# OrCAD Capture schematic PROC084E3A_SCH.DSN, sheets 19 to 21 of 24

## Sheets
19 18. RS485 INTERFACE: size C; title: RS485 INTERFACE
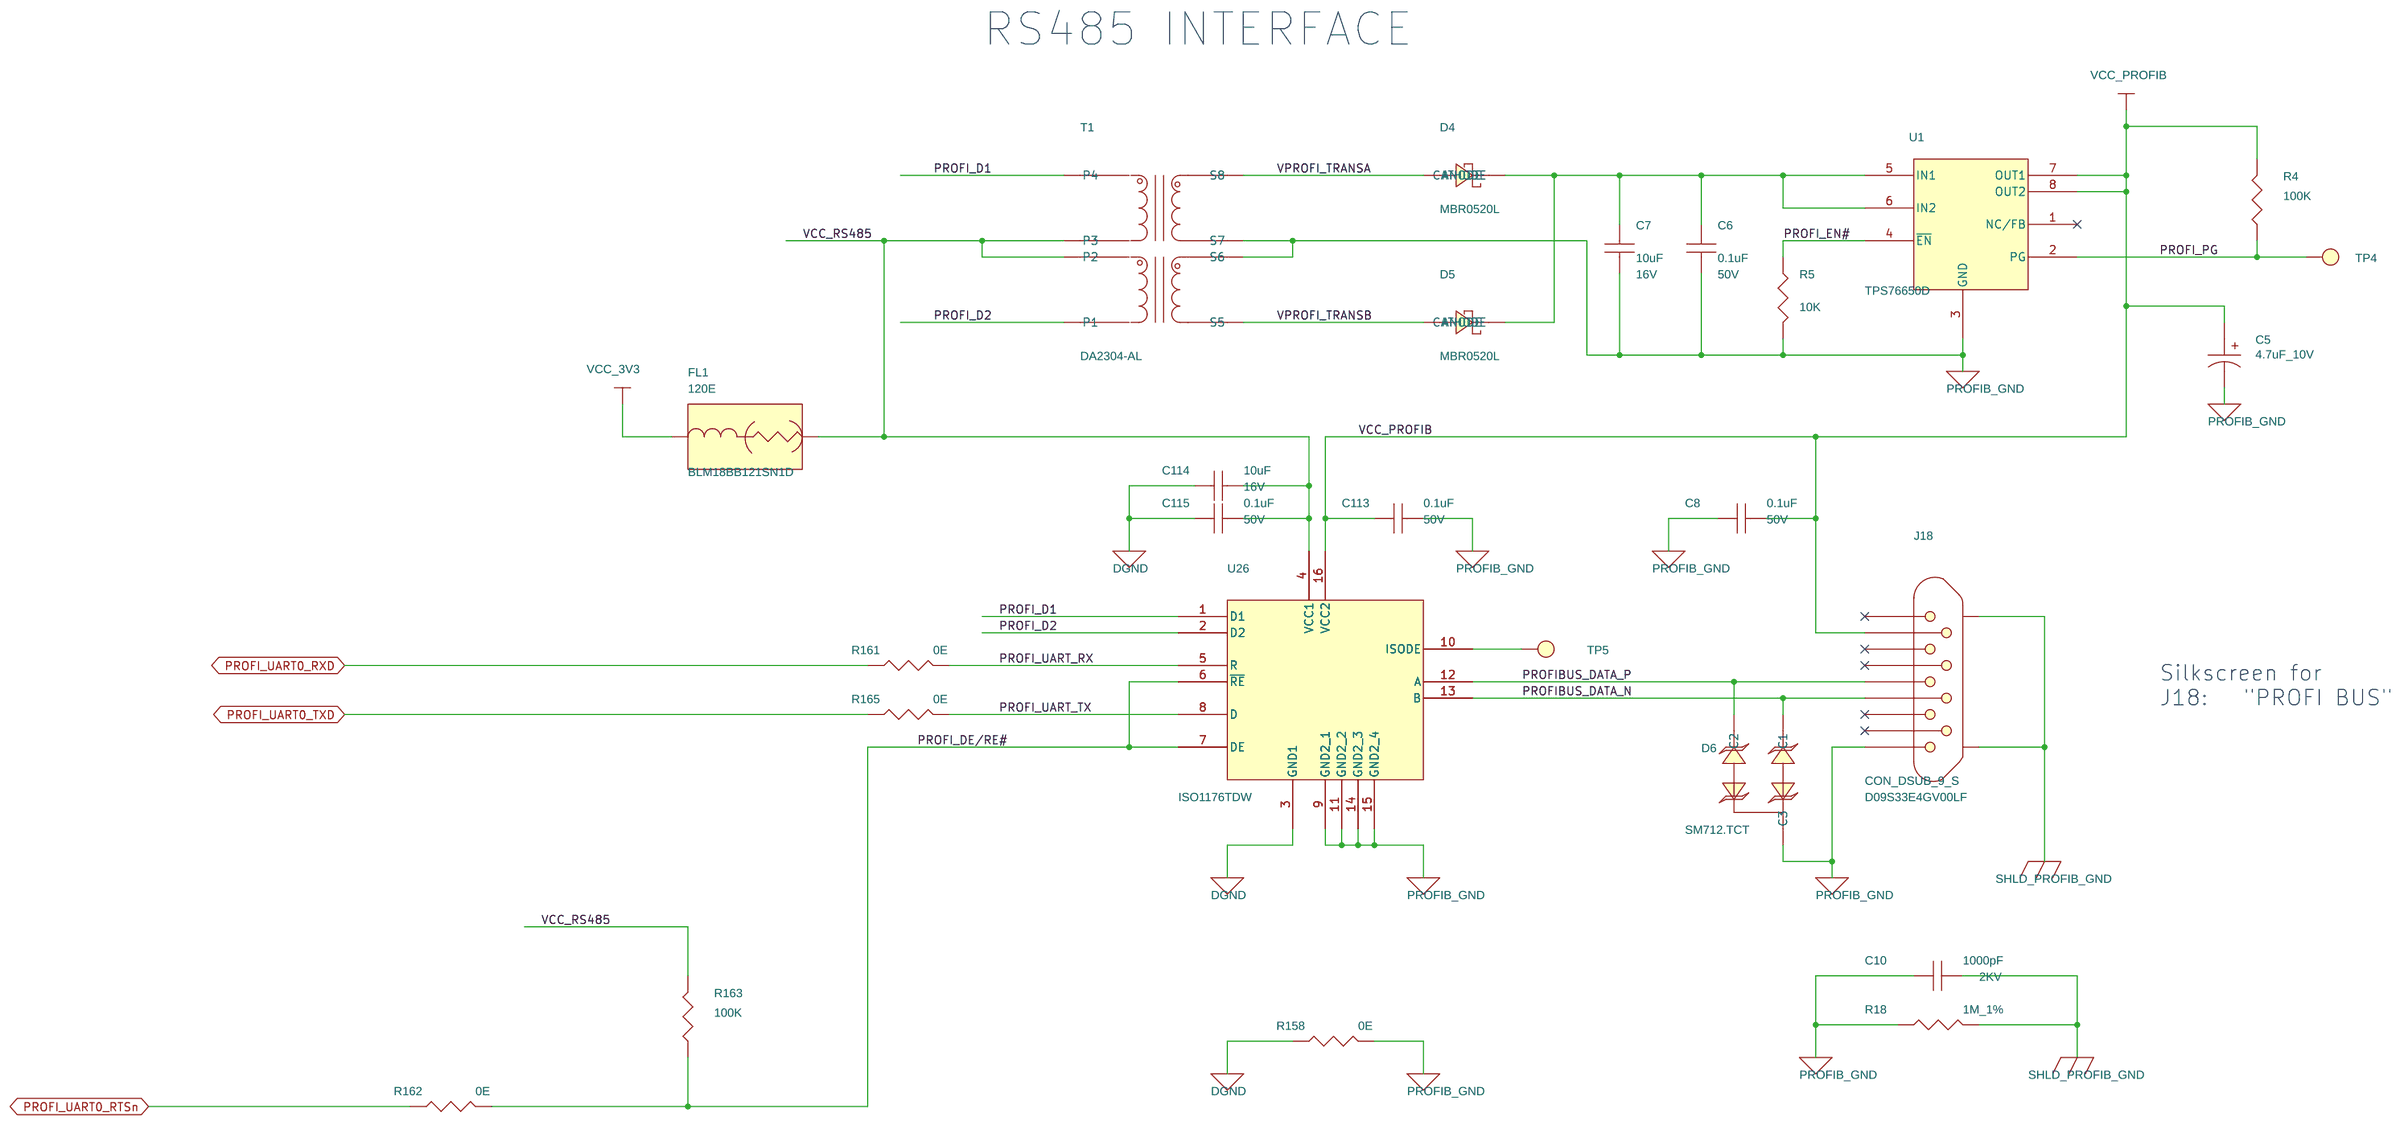
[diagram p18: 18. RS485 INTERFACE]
20 20. BOOSTERPACK HEADER: size C; title: BOOSTERPACK HEADER
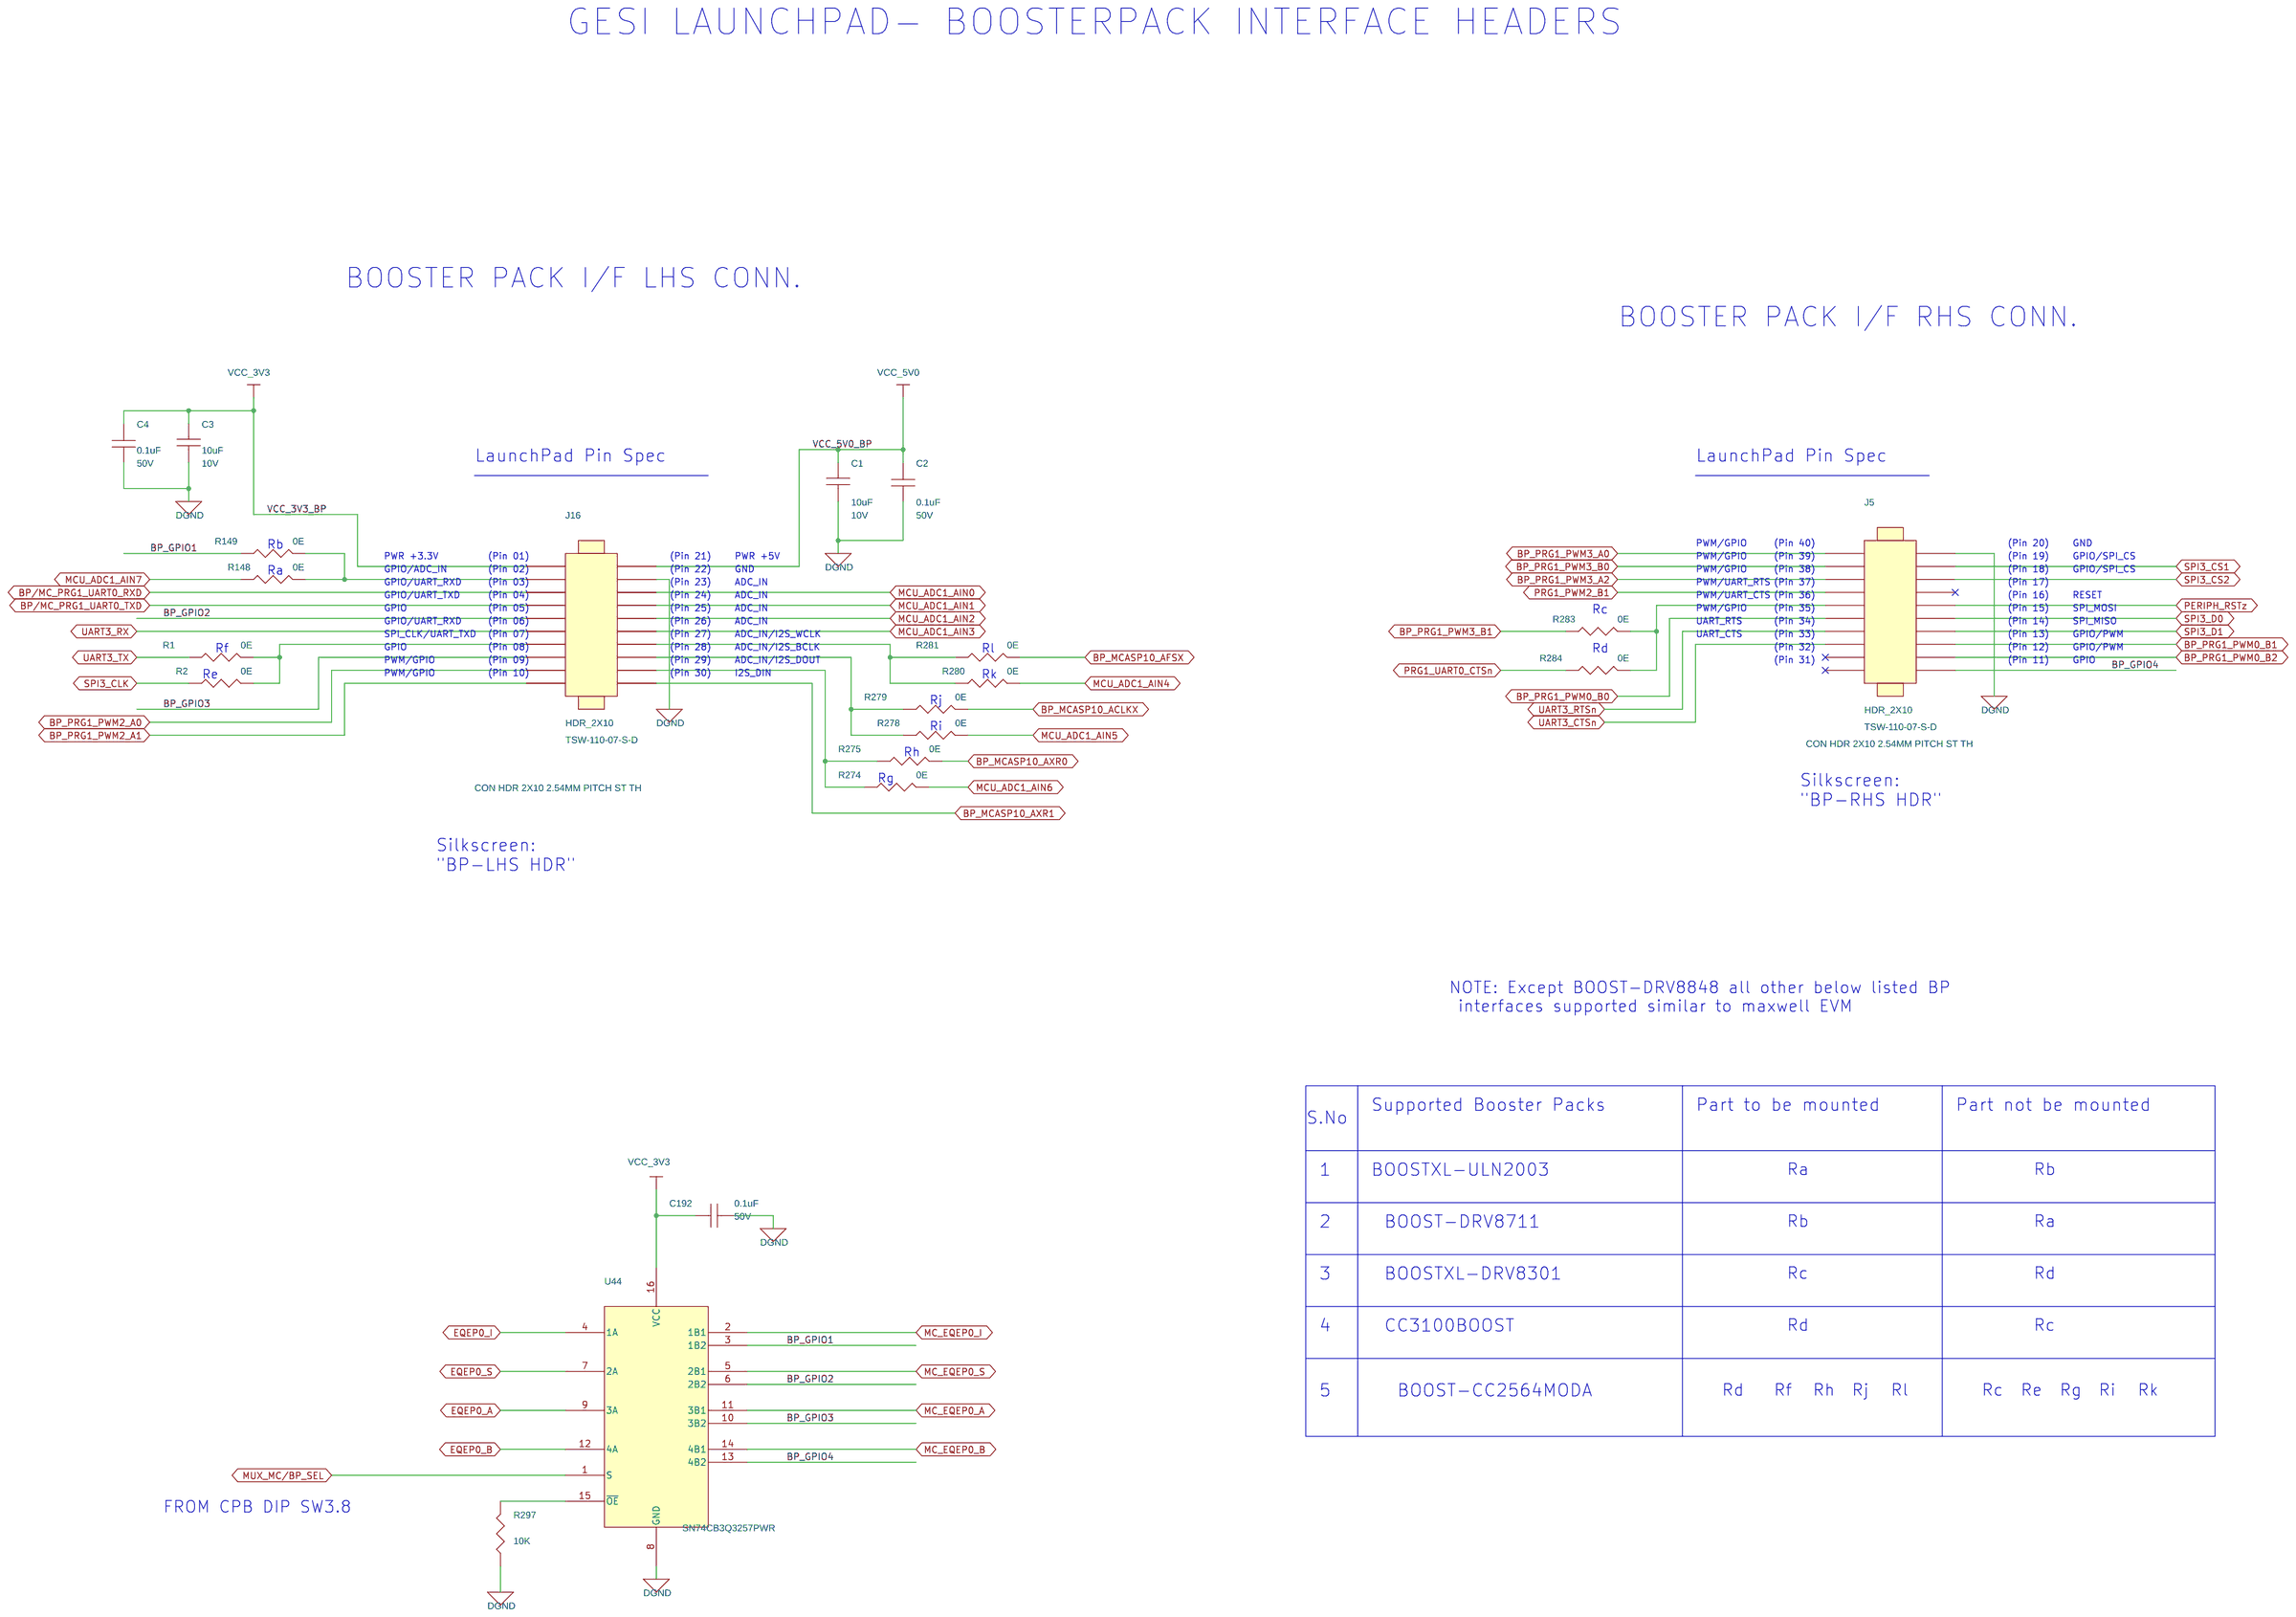
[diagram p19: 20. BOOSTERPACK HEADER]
21 21. ADC_IN: size C; title: ADC IN
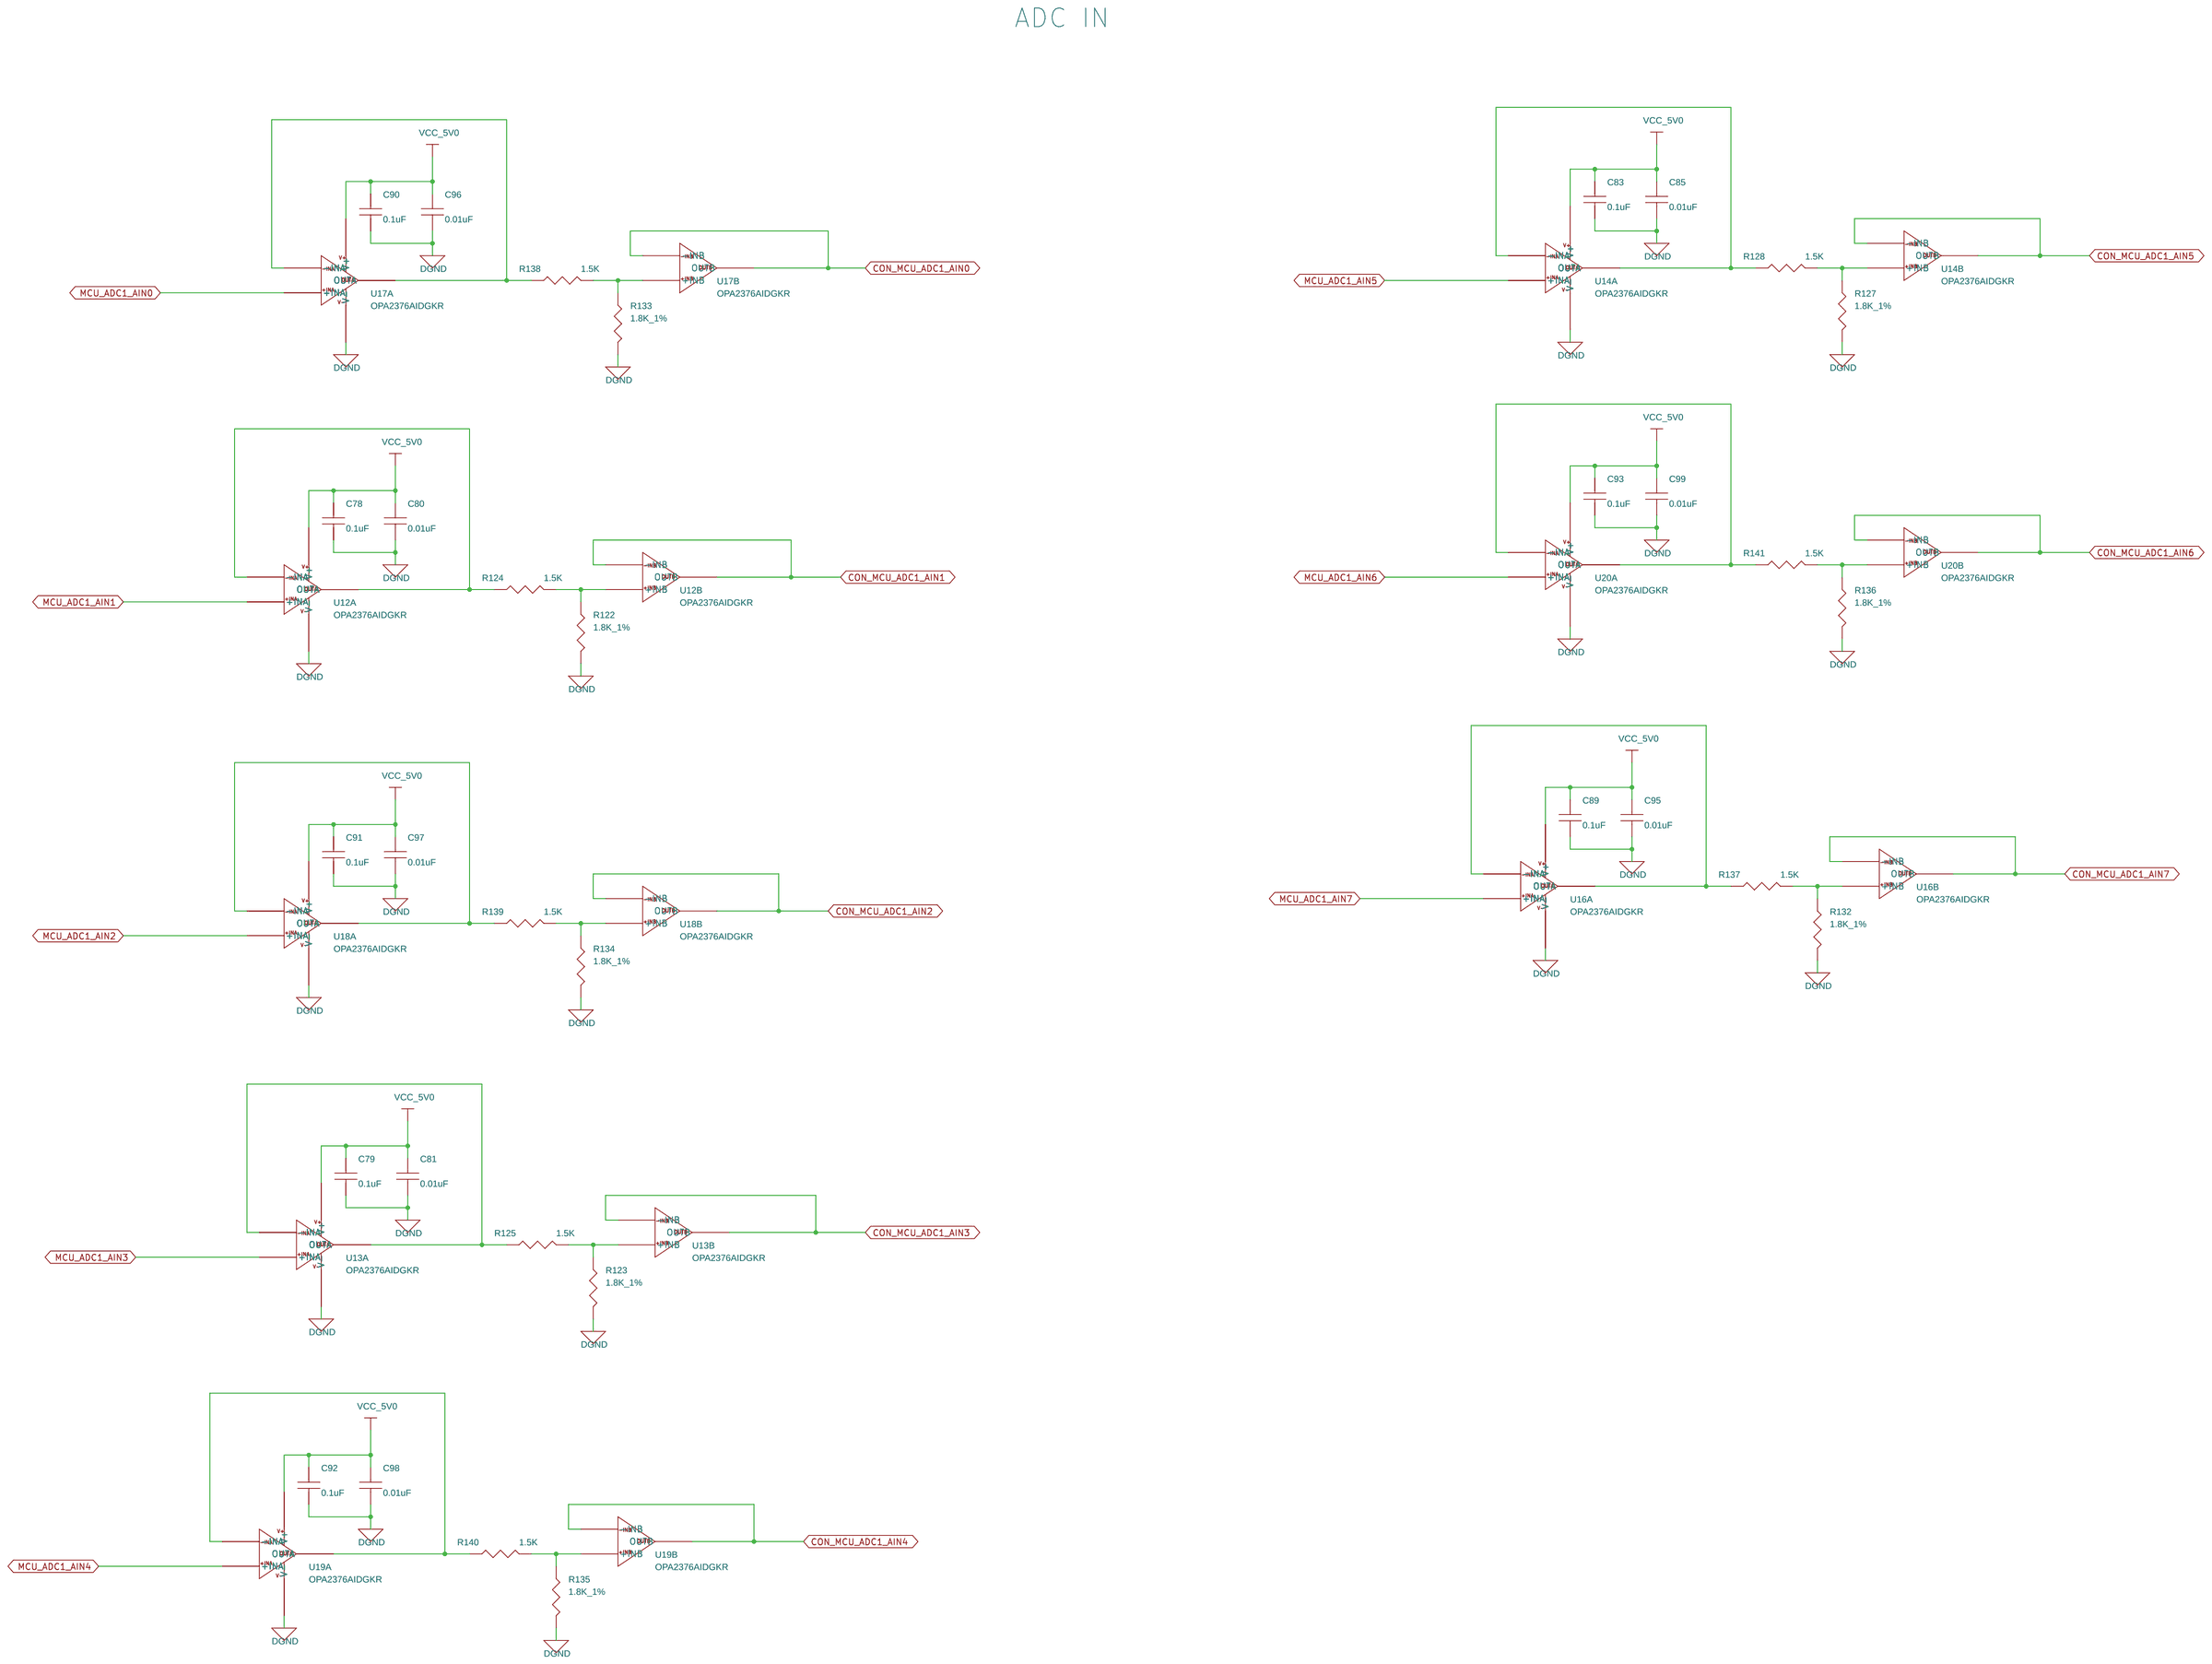
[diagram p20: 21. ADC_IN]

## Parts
sheet 18. RS485 INTERFACE
C5  4.7uF_10V  [CAPT3216A_2]
C6  0.1uF  [CAP0402_0-75]
C7  10uF  [CAP0805_1-5]
C8  0.1uF  [CAP0402_0-75]
C10  1000pF  [CAP1206_1-75]
C113  0.1uF  [CAP0402_0-75]
C114  10uF  [CAP0805_1-5]
C115  0.1uF  [CAP0402_0-75]
D4  MBR0520L  [DIO_SOD123]
D5  MBR0520L  [DIO_SOD123]
D6  SM712.TCT  [DIO_SOT23_123]
FL1  120E  [EMIFIL_BLM18A_0603]
J18  CON_DSUB_9_S  [CON_DB9_D09S33E4GV_S_R_T]
R4  100K  [RES0402_0-5]
R5  10K  [RES0402_0-5]
R18  1M_1%  [RES0805_0-75]
R158  0E  [RES0402_0-5]
R161  0E  [RES0402_0-5]
R162  0E  [RES0402_0-5]
R163  100K  [RES0402_0-5]
R165  0E  [RES0402_0-5]
T1  DA2304-AL  [XFMR8_DA2303-A_320X390_SMD_6]
TP4  TP40_SMD  [TP40_SMD]
TP5  TP40_SMD  [TP40_SMD]
U1  TPS76650D  [SOIC8]
U26  ISO1176TDW  [SOIC16_W]
sheet 20. BOOSTERPACK HEADER
C1  10uF  [CAP0402_0-75]
C2  0.1uF  [CAP0402_0-75]
C3  10uF  [CAP0402_0-75]
C4  0.1uF  [CAP0402_0-75]
C192  0.1uF  [CAP0402_0-75]
J5  HDR_2X10  [HDR_2X10_TSW_100_S_T]
J16  HDR_2X10  [HDR_2X10_TSW_100_S_T]
R1  0E  [RES0402_0-5]
R2  0E  [RES0402_0-5]
R148  0E  [RES0402_0-5]
R149  0E  [RES0402_0-5]
R274  0E  [RES0402_0-5]
R275  0E  [RES0402_0-5]
R278  0E  [RES0402_0-5]
R279  0E  [RES0402_0-5]
R280  0E  [RES0402_0-5]
R281  0E  [RES0402_0-5]
R283  0E  [RES0402_0-5]
R284  0E  [RES0402_0-5]
R297  10K  [RES0402_0-5]
U44  SN74CB3Q3257PWR  [TSSOP16_25-59_205X180]
sheet 21. ADC_IN
C78  0.1uF  [CAP0402_0-75]
C79  0.1uF  [CAP0402_0-75]
C80  0.01uF  [CAP0402_0-75]
C81  0.01uF  [CAP0402_0-75]
C83  0.1uF  [CAP0402_0-75]
C85  0.01uF  [CAP0402_0-75]
C89  0.1uF  [CAP0402_0-75]
C90  0.1uF  [CAP0402_0-75]
C91  0.1uF  [CAP0402_0-75]
C92  0.1uF  [CAP0402_0-75]
C93  0.1uF  [CAP0402_0-75]
C95  0.01uF  [CAP0402_0-75]
C96  0.01uF  [CAP0402_0-75]
C97  0.01uF  [CAP0402_0-75]
C98  0.01uF  [CAP0402_0-75]
C99  0.01uF  [CAP0402_0-75]
R122  1.8K_1%  [RES0402_0-5]
R123  1.8K_1%  [RES0402_0-5]
R124  1.5K  [RES0402_0-5]
R125  1.5K  [RES0402_0-5]
R127  1.8K_1%  [RES0402_0-5]
R128  1.5K  [RES0402_0-5]
R132  1.8K_1%  [RES0402_0-5]
R133  1.8K_1%  [RES0402_0-5]
R134  1.8K_1%  [RES0402_0-5]
R135  1.8K_1%  [RES0402_0-5]
R136  1.8K_1%  [RES0402_0-5]
R137  1.5K  [RES0402_0-5]
R138  1.5K  [RES0402_0-5]
R139  1.5K  [RES0402_0-5]
R140  1.5K  [RES0402_0-5]
R141  1.5K  [RES0402_0-5]
U12  OPA2376AIDGKR  [VSSOP8_25-59_120X120_1-1]  (sections A,B)
U13  OPA2376AIDGKR  [VSSOP8_25-59_120X120_1-1]  (sections A,B)
U14  OPA2376AIDGKR  [VSSOP8_25-59_120X120_1-1]  (sections A,B)
U16  OPA2376AIDGKR  [VSSOP8_25-59_120X120_1-1]  (sections A,B)
U17  OPA2376AIDGKR  [VSSOP8_25-59_120X120_1-1]  (sections A,B)
U18  OPA2376AIDGKR  [VSSOP8_25-59_120X120_1-1]  (sections A,B)
U19  OPA2376AIDGKR  [VSSOP8_25-59_120X120_1-1]  (sections A,B)
U20  OPA2376AIDGKR  [VSSOP8_25-59_120X120_1-1]  (sections A,B)

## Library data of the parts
C5 = CAP_POL: CAP TANTALUM 4.7uF 10V 10% ESR 5E A3216; Chkd/date: MANIRAJA/161017; Crtd /date: MAZHAR/080806; Custom_Duty: 15%; Customs_HS_Code: 85322990; Distributor_name: DIGIKEY; Distributor_part_number: 399-3696-1-ND; Footprint Path: Y:\MIS_DATABASE\Library\ALTIUM_TOOL\PCB_FOOTPRINTS\Altium_Footprint_Lib.PcbLib; Height: 1.80MM; Library Path: Y:\MIS_DATABASE\Library\ALTIUM_TOOL\SCHEMATICS_PARTS\MS_DISCRETE_Library.schlib; Mfr_name: KEMET; Mfr_part_number: T491A475K010AT; Mistral Part No: 120009080027-R; Package: A3216; Part_type: CAPACITORS\TANTALUM; Project: SVDO_RMB_MMA; RoHS: RoHS; Temperature: -55°C+125°C; Tolerance: 10%; Voltage: 10V; Wattage: NA; Weight: 16.2mg; Datasheet: Y:\MIS_DATABASE\DATASHEETS\CAPACITORS\KEMET_T491_MAR18.PDF
C2 C4 C6 C8 C113 C115 C192 = CAP: CAP CERAMIC 0.1uF 50V 10% X7R 0402; Chkd/date: VASANTHA/281216; Crtd /date: CHAITHANYA/051011; Custom_Duty: 15%; Customs_HS_Code: 85322990; Distributor_name: DIGIKEY; Distributor_part_number: 445-173610-1-ND; Footprint Path: Y:\MIS_DATABASE\Library\ALTIUM_TOOL\PCB_FOOTPRINTS\Altium_Footprint_Lib.PcbLib; Height: 0.60MM; Library Path: Y:\MIS_DATABASE\Library\ALTIUM_TOOL\SCHEMATICS_PARTS\MS_DISCRETE_Library.schlib; Mfr_name: TDK CORPORATION; Mfr_part_number: C1005X7R1H104K050BE; Mistral Part No: 120011100014-R; Package: 0402; Part_type: CAPACITORS\CERAMIC; Project: VP-4000-BASE-BOARD; RoHS: RoHS; Temperature: -55°C+125°C; Tolerance: 10%; Voltage: 50V; Wattage: NA; Weight: 0.65mg; Datasheet: Y:\MIS_DATABASE\DATASHEETS\CAPACITORS\TDK_C-SER_FEB19.PDF
C7 C114 = CAP: CAP CERAMIC 10uF 16V 10% X5R 0805; Chkd/date: SHREESHAIL/220506; Crtd /date: MAZHAR/150506; Custom_Duty: 15%; Customs_HS_Code: 85322990; Distributor_name: DIGIKEY; Distributor_part_number: 490-3886-1-ND; Footprint Path: Y:\MIS_DATABASE\Library\ALTIUM_TOOL\PCB_FOOTPRINTS\Altium_Footprint_Lib.PcbLib; Height: 1.35MM; Library Path: Y:\MIS_DATABASE\Library\ALTIUM_TOOL\SCHEMATICS_PARTS\MS_DISCRETE_Library.schlib; Mfr_name: MURATA; Mfr_part_number: GRM21BR61C106KE15L; Mistral Part No: 120009030205-R; Package: 0805; Part_type: CAPACITORS\CERAMIC; Project: VOCERA; RoHS: RoHS; Temperature: -55°C+85°C; Tolerance: 10%; Voltage: 16V; Wattage: NA; Weight: 9.5mg; Datasheet: Y:\MIS_DATABASE\DATASHEETS\CAPACITORS\MURATA-GXX-SER_NOV17.PDF
C10 = CAP: CAP CERAMIC 1000pF 2KV 10% X7R 1206; Chkd/date: SHREESHAIL/291106; Crtd /date: MAZHAR/281106; Custom_Duty: 15%; Customs_HS_Code: 85322990; Distributor_name: DIGIKEY; Distributor_part_number: 478-2956-1-ND; Footprint Path: Y:\MIS_DATABASE\Library\ALTIUM_TOOL\PCB_FOOTPRINTS\Altium_Footprint_Lib.PcbLib; Height: 1.52MM; Library Path: Y:\MIS_DATABASE\Library\ALTIUM_TOOL\SCHEMATICS_PARTS\MS_DISCRETE_Library.schlib; Mfr_name: AVX CORPORATION; Mfr_part_number: 1206GC102KAT1A; Mistral Part No: 120015080006-R; Package: 1206; Part_type: CAPACITORS\CERAMIC; Project: ADR1B; RoHS: RoHS; Temperature: -55°C+125°C; Tolerance: 10%; Voltage: 2KV; Wattage: NA; Weight: 16.2mg; Datasheet: Y:\MIS_DATABASE\DATASHEETS\CAPACITORS\AVX_HV-MLC.PDF
D4 D5 = DIODE_SCHOTTKY: DIODE SCHOTTKY 20V 0.5A SOD123; Chkd/date: SHREESHAIL/291106; Crtd /date: MAZHAR/281106; Custom_Duty: 15%; Customs_HS_Code: 85412900; Distributor_name: DIGIKEY; Distributor_part_number: MBR0520LCT-ND; Height: 1.27MM; Mfr_name: FAIRCHILD; Mistral Part No: 130009030205; Package: SOD123; Part_type: DIODE\SCHOTTKY; Project: LTS; Voltage: 20V; Datasheet: Y:\MIS_DATABASE\DATASHEETS\DISCRETES\DIODES\MBR0520L.PDF
D6 = DIODE_SM712_TVS: DIODE TVS ASYMM RS-485V 7/12V SOT23; Chkd/date: SUHAS/061010; Crtd /date: MAZHAR/030210; Custom_Duty: 15%; Customs_HS_Code: 85412900; Distributor_name: DIGIKEY; Distributor_part_number: SM712CT-ND; Height: 1.12MM; Mfr_name: SEMTECH; Mistral Part No: 130010020003-R; Package: SOT23-3; Part_type: DIODE; Project: OMAPL138; RoHS: Pb-Free; Temperature: -55°C+125°C; Datasheet: Y:\MIS_DATABASE\DATASHEETS\DISCRETES\DIODES\SM712.PDF
FL1 = EMIFILTER_IND: PASSIVE FILTER EMI 120E 0603; Chkd/date: MAZHAR/030809; Crtd /date: USMAN/070109; Custom_Duty: 24%; Customs_HS_Code: 85437099; Distributor_name: DIGIKEY; Distributor_part_number: 490-1020-1-ND; Height: 0.95MM; Mfr_name: MURATA; Mfr_part_number: BLM18BB121SN1D; Mistral Part No: 130009030758; Package: 0603; Part_type: FILTER; Project: OMAP_EVM; Datasheet: Y:\MIS_DATABASE\DATASHEETS\ICS\MISC\BLM18B.PDF
J18 = CON_D9F_RT_TH: CON DSUB 9POS FEMALE RT TH; Chkd/date: JEBRAN/300915; Crtd /date: JEBRAN/300915; Custom_Duty: 24%; Customs_HS_Code: 85369090; Distributor_name: DIGIKEY; Distributor_part_number: 609-1486-ND; Height: 12.58MM; Mfr_name: FCI; Mfr_part_number: D09S33E4GV00LF; Mistral Part No: 150015100004; Package: THRU HOLE; Part_type: CONNECTOR\DSUB; Project: DEBEL_GCS; Temperature: NA; Tolerance: NA; Voltage: NA; Wattage: NA; Weight: NA; Datasheet: Y:\MIS_DATABASE\DATASHEETS\CONNECTORS\D09S33E4GV00LF.PDF
R4 R163 = RESISTOR: RES 100K 1/16W 5% 0402; Chkd/date: VASANTHA/130516; Crtd /date: VASANTHA/130516; Custom_Duty: 15%; Customs_HS_Code: 85332119; Distributor_name: DIGIKEY; Distributor_part_number: A121521CT-ND; Footprint Path: Y:\MIS_DATABASE\Library\ALTIUM_TOOL\PCB_FOOTPRINTS\Altium_Footprint_Lib.PcbLib; Height: 0.40MM; Library Path: Y:\MIS_DATABASE\Library\ALTIUM_TOOL\SCHEMATICS_PARTS\MS_DISCRETE_Library.schlib; Mfr_name: TE CONNECTIVITY; Mfr_part_number: CRG0402J100K/10; Mistral Part No: 110019040062-R; Package: 0402; Part_type: RESISTORS\FIXED; Project: TMDXCSK368; RoHS: RoHS; Temperature: -55°C+125°C; Tolerance: 5%; Voltage: NA; Wattage: 1/16W; Weight: 0.65mg; Datasheet: Y:\MIS_DATABASE\DATASHEETS\RESISTORS\CRG-SERIES.PDF
R5 R297 = RESISTOR: RES 10K 1/16W 5% 0402; Chkd/date: VASANTHA/061216; Crtd /date: MAZHAR/230805; Custom_Duty: 15%; Customs_HS_Code: 85332119; Distributor_name: DIGIKEY; Distributor_part_number: 311-10KJRCT-ND; Footprint Path: Y:\MIS_DATABASE\Library\ALTIUM_TOOL\PCB_FOOTPRINTS\Altium_Footprint_Lib.PcbLib; Height: 0.40MM; Library Path: Y:\MIS_DATABASE\Library\ALTIUM_TOOL\SCHEMATICS_PARTS\MS_DISCRETE_Library.schlib; Mfr_name: YAGEO AMERICA; Mfr_part_number: RC0402JR-0710KL; Mistral Part No: 110011060021-R; Package: 0402; Part_type: RESISTORS\FIXED; Project: HSE; RoHS: RoHS; Temperature: -55°C+155°C; Tolerance: 5%; Voltage: NA; Wattage: 1/16W; Weight: 0.65mg; Datasheet: Y:\MIS_DATABASE\DATASHEETS\RESISTORS\RCXXXXL-SER_MAR18.PDF
R18 = RESISTOR: RES 1M 1/8W 1% 0805; Chkd/date: VASANTHA/150514; Crtd /date: BALACHANDAR/150514; Custom_Duty: 15%; Customs_HS_Code: 85332119; Distributor_name: DIGIKEY; Distributor_part_number: P1.00MCCT-ND; Footprint Path: Y:\MIS_DATABASE\Library\ALTIUM_TOOL\PCB_FOOTPRINTS\Altium_Footprint_Lib.PcbLib; Height: 0.70MM; Library Path: Y:\MIS_DATABASE\Library\ALTIUM_TOOL\SCHEMATICS_PARTS\MS_DISCRETE_Library.schlib; Mfr_name: PANASONIC-ECG; Mfr_part_number: ERJ-6ENF1004V; Mistral Part No: 110014100002-R; Package: 0805; Part_type: RESISTORS\FIXED; Project: HUMANWARE_PHOENIX; RoHS: RoHS; Temperature: -55°C+155°C; Tolerance: 1%; Voltage: NA; Wattage: 1/8W; Weight: 4mg; Datasheet: Y:\MIS_DATABASE\DATASHEETS\RESISTORS\PAN-ERJSER_NOV17.PDF
R158 = RESISTOR: RES 0E 1/10W JUMPER 0402; Assembly_Instruction: DNI; Chkd/date: MANIRAJA/290318; Crtd /date: ALVY/270318; Custom_Duty: 15%; Customs_HS_Code: 85332119; Distributor_name: DIGIKEY; Distributor_part_number: MCS0402-0.0-ZZCT-ND; Footprint Path: Y:\MIS_DATABASE\Library\ALTIUM_TOOL\PCB_FOOTPRINTS\Altium_Footprint_Lib.PcbLib; Height: 0.37MM; Library Path: Y:\MIS_DATABASE\Library\ALTIUM_TOOL\SCHEMATICS_PARTS\MS_DISCRETE_Library.schlib; Mfr_name: VISHAY; Mfr_part_number: MCS04020Z0000ZE000; Mistral Part No: 110018030052-R; Package: 0402; Part_type: RESISTORS\FIXED; Project: DRDL_ITS2-SC; RoHS: RoHS; SIGNAL_MODEL: INS23888567; Temperature: -55°C+155°C; Tolerance: NA; Voltage: NA; Wattage: 1/10W; Weight: 0.65mg; Datasheet: Y:\MIS_DATABASE\DATASHEETS\RESISTORS\MCTXXXXC-SER.PDF
R161 R162 R165 = RESISTOR: RES 0E 1/10W JUMPER 0402; Chkd/date: MANIRAJA/290318; Crtd /date: ALVY/270318; Custom_Duty: 15%; Customs_HS_Code: 85332119; Distributor_name: DIGIKEY; Distributor_part_number: MCS0402-0.0-ZZCT-ND; Footprint Path: Y:\MIS_DATABASE\Library\ALTIUM_TOOL\PCB_FOOTPRINTS\Altium_Footprint_Lib.PcbLib; Height: 0.37MM; Library Path: Y:\MIS_DATABASE\Library\ALTIUM_TOOL\SCHEMATICS_PARTS\MS_DISCRETE_Library.schlib; Mfr_name: VISHAY; Mfr_part_number: MCS04020Z0000ZE000; Mistral Part No: 110018030052-R; Package: 0402; Part_type: RESISTORS\FIXED; Project: DRDL_ITS2-SC; RoHS: RoHS; SIGNAL_MODEL: INS23888567; Temperature: -55°C+155°C; Tolerance: NA; Voltage: NA; Wattage: 1/10W; Weight: 0.65mg; Datasheet: Y:\MIS_DATABASE\DATASHEETS\RESISTORS\MCTXXXXC-SER.PDF
T1 = TRANS_DA2303-AL: TRANSFORMER POWER SMD; Chkd/date: MANIRAJA/150917; Crtd /date: VASANTHA/071014; Distributor_name: NA; Distributor_part_number: NA; Height: 5.97MM; Mfr_name: COIL CRAFT; Mistral Part No: 130014100010-R; Package: SMD; Part_type: TRANSFORMER; Project: AEGIS_POM; RoHS: RoHS; Temperature: -40°C+125°C; Tolerance: NA; Voltage: NA; Wattage: NA; Weight: 1g; Datasheet: Y:\MIS_DATABASE\DATASHEETS\ICS\MISC\DA2303-AL.PDF
TP4 TP5 = TESTPOINT: TESTPOINT CIR 40 SMD; Chkd/date: MAZHAR/190505; Crtd /date: MAZHAR/190505; Distributor_name: NA; Distributor_part_number: NA; Footprint Path: Y:\MIS_DATABASE\Library\ALTIUM_TOOL\PCB_FOOTPRINTS\Altium_Footprint_Lib.PcbLib; Height: NA; Library Path: Y:\MIS_DATABASE\Library\ALTIUM_TOOL\SCHEMATICS_PARTS\MS_DISCRETE_Library.schlib; MECHANICAL 3D STEP FILE: NA; Mfr_name: LOCAL; Mistral Part No: 130009030933; Package: SMD; Project: RAINIER-3; RoHS: NA; Temperature: NA; Tolerance: NA; Voltage: NA; Wattage: NA; Weight: NA; Datasheet: NA
U1 = TPS766_SOIC8: IC LDO VOLTAGE REGULATOR 5V 250mA SOIC8; Chkd/date: RAGESH/201010; Crtd /date: MAZHAR/030210; Custom_Duty: 15%; Customs_HS_Code: 85423100; Distributor_name: DIGIKEY; Distributor_part_number: 296-2730-5-ND; Height: 1.75MM; Mfr_name: TEXAS INSTRUMENTS; Mistral Part No: 142010020006-R; Part_type: ICS\POWER\VOLTAGE REGULATOR; Project: OMAPL138; RoHS: RoHS; Temperature: -40°C+125°C; Weight: NA; Datasheet: Y:\MIS_DATABASE\DATASHEETS\MISC\REGULATORS\TPS766.PDF
U26 = ISO1177DW_SOIC16: IC ISOLATED RS-485 PROFIBUS TRANSCEIVER SOIC16; Chkd/date: NAVEED/22014; Crtd /date: VASANTHA/111014; Custom_Duty: 15%; Customs_HS_Code: 85423100; Distributor_name: DIGIKEY; Distributor_part_number: 296-28103-5-ND; Height: 2.65MM; Mfr_name: TEXAS INSTRUMENTS; Mistral Part No: 141014100007-R; Package: SOIC16; Part_type: ICS\INTERFACE\LINE DRIVER; Project: AEGIS_POM; RoHS: RoHS; Temperature: -40°C+85°C; Tolerance: NA; Voltage: NA; Wattage: NA; Weight: NA; Datasheet: Y:\MIS_DATABASE\DATASHEETS\ICS\INTERFACE\ISO1176TDW.PDF
C1 C3 = CAP: CAP CERAMIC 10uF 10V 20% X5R 0402; Chkd/date: VASANTHA/291216; Crtd /date: USMAN/261113; Custom_Duty: 15%; Customs_HS_Code: 85322990; Distributor_name: DIGIKEY; Distributor_part_number: 1276-1450-1-ND; Footprint Path: Y:\MIS_DATABASE\Library\ALTIUM_TOOL\PCB_FOOTPRINTS\Altium_Footprint_Lib.PcbLib; Height: 0.55MM; Library Path: Y:\MIS_DATABASE\Library\ALTIUM_TOOL\SCHEMATICS_PARTS\MS_DISCRETE_Library.schlib; Mfr_name: SAMSUNG; Mfr_part_number: CL05A106MP5NUNC; Mistral Part No: 120013110019-R; Package: 0402; Part_type: CAPACITORS\CERAMIC; Project: C-BAND_SYNTH; RoHS: RoHS; Temperature: -55°C+85°C; Tolerance: 20%; Voltage: 10V; Wattage: NA; Weight: 0.65mg; Datasheet: Y:\MIS_DATABASE\DATASHEETS\CAPACITORS\CL05A106MP5NUNC.PDF
J5 J16 = HEADER_10X2: CON HDR 2X10 2.54MM PITCH ST TH; Chkd/date: NAVEED/140515; Crtd /date: MAZHAR/020909; Custom_Duty: 0.24; Customs_HS_Code: 85369090; Distributor_name: DIGIKEY; Distributor_part_number: SAM1032-10-ND; Height: 5.02MM; Mfr_name: SAMTEC; Mfr_part_number: TSW-110-07-S-D; Mistral Part No: 150009090001-R; Package: THRU-HOLE; Part_type: CONNECTOR\HEADERS; Project: SMART VIEW_NVR; RoHS: RoHS; Temperature: NA; Tolerance: NA; Voltage: NA; Wattage: NA; Weight: NA; Datasheet: Y:\MIS_DATABASE\DATASHEETS\CONNECTORS\TSW-106-23-T-S.PDF
R1 R149 R275 R279 R281 R284 = RESISTOR: RES 0E 1/10W JUMPER 0402; Assembly_Instruction: DNI; Chkd/date: MANIRAJA/290318; Crtd /date: ALVY/270318; Custom_Duty: 15%; Customs_HS_Code: 85332119; Distributor_name: DIGIKEY; Distributor_part_number: MCS0402-0.0-ZZCT-ND; Footprint Path: Y:\MIS_DATABASE\Library\ALTIUM_TOOL\PCB_FOOTPRINTS\Altium_Footprint_Lib.PcbLib; Height: 0.37MM; Library Path: Y:\MIS_DATABASE\Library\ALTIUM_TOOL\SCHEMATICS_PARTS\MS_DISCRETE_Library.schlib; Mfr_name: VISHAY; Mfr_part_number: MCS04020Z0000ZE000; Mistral Part No: 110018030052-R; Package: 0402; Part_type: RESISTORS\FIXED; Project: DRDL_ITS2-SC; RoHS: RoHS; Temperature: -55°C+155°C; Tolerance: NA; Voltage: NA; Wattage: 1/10W; Weight: 0.65mg; Datasheet: Y:\MIS_DATABASE\DATASHEETS\RESISTORS\MCTXXXXC-SER.PDF
R2 R148 R274 R278 R280 R283 = RESISTOR: RES 0E 1/10W JUMPER 0402; Chkd/date: MANIRAJA/290318; Crtd /date: ALVY/270318; Custom_Duty: 15%; Customs_HS_Code: 85332119; Distributor_name: DIGIKEY; Distributor_part_number: MCS0402-0.0-ZZCT-ND; Footprint Path: Y:\MIS_DATABASE\Library\ALTIUM_TOOL\PCB_FOOTPRINTS\Altium_Footprint_Lib.PcbLib; Height: 0.37MM; Library Path: Y:\MIS_DATABASE\Library\ALTIUM_TOOL\SCHEMATICS_PARTS\MS_DISCRETE_Library.schlib; Mfr_name: VISHAY; Mfr_part_number: MCS04020Z0000ZE000; Mistral Part No: 110018030052-R; Package: 0402; Part_type: RESISTORS\FIXED; Project: DRDL_ITS2-SC; RoHS: RoHS; Temperature: -55°C+155°C; Tolerance: NA; Voltage: NA; Wattage: 1/10W; Weight: 0.65mg; Datasheet: Y:\MIS_DATABASE\DATASHEETS\RESISTORS\MCTXXXXC-SER.PDF
U44 = SN74CB3Q3257PWR_TSSOP16: IC 4BIT 1-OF-2 FET MULTIPLEXER/DEMULTIPLEXER TSSOP16; Chkd/date: SUHAS/251010; Crtd /date: USMAN/060109; Custom_Duty: 15%; Customs_HS_Code: 85423100; Distributor_name: DIGIKEY; Distributor_part_number: 296-19138-1-ND; Height: 1.20MM; Mfr_name: TEXAS INSTRUMENTS; Mistral Part No: 141009030117-R; Package: TSSOP16; Part_type: ICS\DIGITAL\COMBINATIONAL; Project: OMAP_EVM; RoHS: Sb/ Br FREE; Temperature: -40°C+85°C; Datasheet: Y:\MIS_DATABASE\DATASHEETS\ICS\DIGITAL\COMBINATIONAL\SN74CB3Q3257.PDF
C78 C79 C83 C89-C93 = CAP: CAP CERAMIC 0.1uF 25V 10% X5R 0402; Chkd/date: VASANTHA/291216; Crtd /date: MAZHAR/151206; Custom_Duty: 15%; Customs_HS_Code: 85322990; Distributor_name: DIGIKEY; Distributor_part_number: 587-1456-1-ND; Footprint Path: Y:\MIS_DATABASE\Library\ALTIUM_TOOL\PCB_FOOTPRINTS\Altium_Footprint_Lib.PcbLib; Height: 0.55MM; Library Path: Y:\MIS_DATABASE\Library\ALTIUM_TOOL\SCHEMATICS_PARTS\MS_DISCRETE_Library.schlib; Mfr_name: TAIYO YUDEN; Mfr_part_number: TMK105BJ104KV-F; Mistral Part No: 120017080016-R; Package: 0402; Part_type: CAPACITORS\CERAMIC; Project: ADR1B; RoHS: RoHS; Temperature: -55°C+85°C; Tolerance: 10%; Voltage: 25V; Wattage: NA; Weight: 0.65mg; Datasheet: Y:\MIS_DATABASE\DATASHEETS\CAPACITORS\TMK105BJ104KV-F.PDF
C80 C81 C85 C95-C99 = CAP: CAP CERAMIC 0.01uF 50V 10% X7R 0402; Chkd/date: SHREESHAIL/301105; Crtd /date: MAZHAR/040505; Custom_Duty: 15%; Customs_HS_Code: 85322990; Distributor_name: DIGIKEY; Distributor_part_number: 399-3066-1-ND; Footprint Path: Y:\MIS_DATABASE\Library\ALTIUM_TOOL\PCB_FOOTPRINTS\Altium_Footprint_Lib.PcbLib; Height: 0.55MM; Library Path: Y:\MIS_DATABASE\Library\ALTIUM_TOOL\SCHEMATICS_PARTS\MS_DISCRETE_Library.schlib; Mfr_name: KEMET; Mfr_part_number: C0402C103K5RACTU; Mistral Part No: 120009030025-R; Package: 0402; Part_type: CAPACITORS\CERAMIC; Project: G4_SVGA; RoHS: RoHS; Temperature: -55°C+125°C; Tolerance: 10%; Voltage: 50V; Wattage: NA; Weight: 0.65mg; Datasheet: Y:\MIS_DATABASE\DATASHEETS\CAPACITORS\KEMET-C-X7R.PDF
R122 R123 R127 R132-R136 = RESISTOR: RES 1.8K 1/16W 1% 0402; Chkd/date: MANIRAJA/130617; Crtd /date: BAVISH/040111; Custom_Duty: 15%; Customs_HS_Code: 85332119; Distributor_name: DIGIKEY; Distributor_part_number: 541-1.80KLCT-ND; Footprint Path: Y:\MIS_DATABASE\Library\ALTIUM_TOOL\PCB_FOOTPRINTS\Altium_Footprint_Lib.PcbLib; Height: 0.40MM; Library Path: Y:\MIS_DATABASE\Library\ALTIUM_TOOL\SCHEMATICS_PARTS\MS_DISCRETE_Library.schlib; Mfr_name: VISHAY; Mfr_part_number: CRCW04021K80FKED; Mistral Part No: 110011010002-R; Package: 0402; Part_type: RESISTORS\FIXED; Project: CPCI3GADC_CARD; RoHS: RoHS; Temperature: -55°C+155°C; Tolerance: 1%; Voltage: NA; Wattage: 1/16W; Weight: 0.65mg; Datasheet: Y:\MIS_DATABASE\DATASHEETS\RESISTORS\CRCW0603.PDF
R124 R125 R128 R137-R141 = RESISTOR: RES 1.5K 1/16W 5% 0402; Chkd/date: MANIRAJA/310718; Crtd /date: BAVISH/021210; Custom_Duty: 15%; Customs_HS_Code: 85332119; Distributor_name: DIGIKEY; Distributor_part_number: 311-1.5KJRCT-ND; Footprint Path: Y:\MIS_DATABASE\Library\ALTIUM_TOOL\PCB_FOOTPRINTS\Altium_Footprint_Lib.PcbLib; Height: 0.40MM; Library Path: Y:\MIS_DATABASE\Library\ALTIUM_TOOL\SCHEMATICS_PARTS\MS_DISCRETE_Library.schlib; Mfr_name: YAGEO AMERICA; Mfr_part_number: RC0402JR-071K5L; Mistral Part No: 110010120012-R; Package: 0402; Part_type: RESISTORS\FIXED; Project: TE4; RoHS: RoHS; Temperature: -55°C+155°C; Tolerance: 5%; Voltage: NA; Wattage: 1/16W; Weight: 0.65mg; Datasheet: Y:\MIS_DATABASE\DATASHEETS\RESISTORS\RCXXXXL-SER_MAR18.PDF
U12-U14 U16-U20 = OPA2350UA_SOIC8: IC LOW QUIESCENT CURRENT E-TRIM SERIES OPAMP VSSOP8; Chkd/date: MANIRAJA/021117; Crtd /date: MANIRAJA/021117; Custom_Duty: 15%; Customs_HS_Code: 85423100; Distributor_name: DIGIKEY; Distributor_part_number: 296-22630-1-ND; Height: 1.10MM; Mfr_name: TEXAS INSTRUMENTS; Mistral Part No: 140117110001-R; Package: VSSOP8; Part_type: ICS\ANALOG\OPAMP; Project: TI_MAXIE_CPB; RoHS: RoHS; Temperature: -40°C+125°C; Tolerance: NA; Voltage: NA; Wattage: NA; Weight: 26mg; Datasheet: Y:\MIS_DATABASE\DATASHEETS\ICS\OPAMP\OPA2376XX.PDF

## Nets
DGND: C1.2 C2.1 C3.2 C4.1 C78.2 C79.2 C80.2 C81.2 C83.2 C85.2 C89.2 C90.2 C91.2 C92.2 C93.2 C95.2 C96.2 C97.2 C98.2 C99.2 C114.1 C115.1 C192.2 J5.2 J16.4 R122.2 R123.2 R127.2 R132.2 R133.2 R134.2 R135.2 R136.2 R158.1 R297.1 U12.4(V-) U13.4(V-) U14.4(V-) U16.4(V-) U17.4(V-) U18.4(V-) U19.4(V-) U20.4(V-) U26.3(GND1) U44.8(GND) ; also on sheet 1 2 3 8 9 10 11 12 13 14 15 16 17 18 22 23 24
VCC_3V3: C3.1 C4.2 C192.1 FL1.1 J16.1 U44.16(VCC) ; also on sheet 1 2 3 8 9 10 11 12 13 14 15 16 17 18 22 23 24
VCC_5V0: C1.1 C2.2 C78.1 C79.1 C80.1 C81.1 C83.1 C85.1 C89.1 C90.1 C91.1 C92.1 C93.1 C95.1 C96.1 C97.1 C98.1 C99.1 J16.2 U12.8(V+) U13.8(V+) U14.8(V+) U16.8(V+) U17.8(V+) U18.8(V+) U19.8(V+) U20.8(V+) ; also on sheet 8 17 18 23 24
VCC_PROFIB: C5.1 C8.2 C113.1 J18.6 R4.2 U1.7(OUT1) U1.8(OUT2) U26.16(VCC2)
VCC_RS485: C114.2 C115.2 FL1.2 R163.2 T1.2(P2) T1.3(P3) U26.4(VCC1)
BP/MC_PRG1_UART0_RXD: J16.5 ; also on sheet 10 24
BP/MC_PRG1_UART0_TXD: J16.7 ; also on sheet 10 24
BP_GPIO1: R149.1 U44.3(1B2)
BP_GPIO2: J16.9 U44.6(2B2)
BP_GPIO3: J16.15 U44.10(3B2)
BP_GPIO4: J5.20 U44.13(4B2)
BP_MCASP10_ACLKX: R279.2 ; also on sheet 10
BP_MCASP10_AFSX: R281.2 ; also on sheet 10
BP_MCASP10_AXR0: R275.2 ; also on sheet 10
BP_MCASP10_AXR1: J16.20 ; also on sheet 8
BP_PRG1_PWM0_B0: J5.11 ; also on sheet 10
BP_PRG1_PWM0_B1: J5.16 ; also on sheet 10
BP_PRG1_PWM0_B2: J5.18 ; also on sheet 10
BP_PRG1_PWM2_A0: J16.17 ; also on sheet 10
BP_PRG1_PWM2_A1: J16.19 ; also on sheet 10
BP_PRG1_PWM3_A0: J5.1 ; also on sheet 10
BP_PRG1_PWM3_A2: J5.5 ; also on sheet 10
BP_PRG1_PWM3_B0: J5.3 ; also on sheet 10
BP_PRG1_PWM3_B1: R283.1 ; also on sheet 10
CON_MCU_ADC1_AIN0: U17.6(-INB) U17.7(OUTB) ; also on sheet 8
CON_MCU_ADC1_AIN1: U12.6(-INB) U12.7(OUTB) ; also on sheet 8
CON_MCU_ADC1_AIN2: U18.6(-INB) U18.7(OUTB) ; also on sheet 8
CON_MCU_ADC1_AIN3: U13.6(-INB) U13.7(OUTB) ; also on sheet 8
CON_MCU_ADC1_AIN4: U19.6(-INB) U19.7(OUTB) ; also on sheet 8
CON_MCU_ADC1_AIN5: U14.6(-INB) U14.7(OUTB) ; also on sheet 8
CON_MCU_ADC1_AIN6: U20.6(-INB) U20.7(OUTB) ; also on sheet 8
CON_MCU_ADC1_AIN7: U16.6(-INB) U16.7(OUTB) ; also on sheet 8
EQEP0_A: U44.9(3A) ; also on sheet 8
EQEP0_B: U44.12(4A) ; also on sheet 8
EQEP0_I: U44.4(1A) ; also on sheet 8
EQEP0_S: U44.7(2A) ; also on sheet 8
MC_EQEP0_A: U44.11(3B1) ; also on sheet 24
MC_EQEP0_B: U44.14(4B1) ; also on sheet 24
MC_EQEP0_I: U44.2(1B1) ; also on sheet 24
MC_EQEP0_S: U44.5(2B1) ; also on sheet 24
MCU_ADC1_AIN0: J16.6 U17.3(+INA) ; also on sheet 24
MCU_ADC1_AIN1: J16.8 U12.3(+INA) ; also on sheet 24
MCU_ADC1_AIN2: J16.10 U18.3(+INA) ; also on sheet 24
MCU_ADC1_AIN3: J16.12 U13.3(+INA) ; also on sheet 24
MCU_ADC1_AIN4: R280.2 U19.3(+INA) ; also on sheet 24
MCU_ADC1_AIN5: R278.2 U14.3(+INA) ; also on sheet 24
MCU_ADC1_AIN6: R274.2 U20.3(+INA) ; also on sheet 24
MCU_ADC1_AIN7: R148.1 U16.3(+INA) ; also on sheet 24
MUX_MC/BP_SEL: U44.1(S) ; also on sheet 8 10
PERIPH_RSTz: J5.10 ; also on sheet 8
PRG1_PWM2_B1: J5.7 ; also on sheet 10 24
PRG1_UART0_CTSn: R284.1 ; also on sheet 8
PROFI_D1: T1.4(P4) U26.1(D1)
PROFI_D2: T1.1(P1) U26.2(D2)
PROFI_DE/RE#: R162.2 R163.1 U26.6(~{RE}) U26.7(DE)
PROFI_EN#: R5.1 U1.4(~{EN})
PROFI_PG: R4.1 TP4.1(TP) U1.2(PG)
PROFI_UART0_RTSn: R162.1 ; also on sheet 10
PROFI_UART0_RXD: R161.1 ; also on sheet 10
PROFI_UART0_TXD: R165.1 ; also on sheet 10
PROFI_UART_RX: R161.2 U26.5(R)
PROFI_UART_TX: R165.2 U26.8(D)
PROFIB_GND: C5.2 C6.2 C7.2 C8.1 C10.1 C113.2 D6.3(C3) J18.5 R5.2 R18.1 R158.2 T1.6(S6) T1.7(S7) U1.3(GND) U26.9(GND2_1) U26.11(GND2_2) U26.14(GND2_3) U26.15(GND2_4)
PROFIBUS_DATA_N: D6.1(C1) J18.8 U26.13(B)
PROFIBUS_DATA_P: D6.2(C2) J18.3 U26.12(A)
SHLD_PROFIB_GND: C10.2 J18.10 J18.11 R18.2
SPI3_CLK: R2.1 ; also on sheet 8 24
SPI3_CS1: J5.4 ; also on sheet 8 24
SPI3_CS2: J5.6 ; also on sheet 8
SPI3_D0: J5.12 ; also on sheet 8 24
SPI3_D1: J5.14 ; also on sheet 8 24
UART3_CTSn: J5.15 ; also on sheet 12 24
UART3_RTSn: J5.13 ; also on sheet 12 24
UART3_RX: J16.11 ; also on sheet 9 24
UART3_TX: R1.1 ; also on sheet 9 24
VPROFI_TRANSA: D4.2(ANODE) T1.8(S8)
VPROFI_TRANSB: D5.2(ANODE) T1.5(S5)
N23015059: C6.1 C7.1 D4.1(CATHODE) D5.1(CATHODE) U1.5(IN1) U1.6(IN2)
N23015114: TP5.1(TP) U26.10(ISODE)
N23770248: R138.1 U17.1(OUTA) U17.2(-INA)
N23770260: R133.1 R138.2 U17.5(+INB)
N23770732: R124.1 U12.1(OUTA) U12.2(-INA)
N23770754: R122.1 R124.2 U12.5(+INB)
N23770913: R139.1 U18.1(OUTA) U18.2(-INA)
N23770935: R134.1 R139.2 U18.5(+INB)
N23771115: R125.1 U13.1(OUTA) U13.2(-INA)
N23771129: R123.1 R125.2 U13.5(+INB)
N23772151: R140.1 U19.1(OUTA) U19.2(-INA)
N23772167: R135.1 R140.2 U19.5(+INB)
N23772825: R128.1 U14.1(OUTA) U14.2(-INA)
N23772836: R127.1 R128.2 U14.5(+INB)
N23773069: R141.1 U20.1(OUTA) U20.2(-INA)
N23773080: R136.1 R141.2 U20.5(+INB)
N23773321: R137.1 U16.1(OUTA) U16.2(-INA)
N23773334: R132.1 R137.2 U16.5(+INB)
N23773620: J16.14 R280.1 R281.1
N23773629: J16.16 R278.1 R279.1
N23773638: J16.18 R274.1 R275.1
N23842091: J16.3 R148.2 R149.2
N23842425: J16.13 R1.2 R2.2
N23918331: J5.9 R283.2 R284.2
N23981235: R297.2 U44.15(~{OE})

Not connected (* = marked no-connect by the designer): J5 8* 17* 19*; J18 1* 2* 4* 7* 9*; U1 1(NC/FB)*

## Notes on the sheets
sheet 19
- RS485 INTERFACE
- Silkscreen for
  J18:   "PROFI BUS"
sheet 20
- GESI LAUNCHPAD- BOOSTERPACK INTERFACE HEADERS
- BOOSTER PACK I/F LHS CONN.
- BOOSTER PACK I/F RHS CONN.
- LaunchPad Pin Spec
- LaunchPad Pin Spec
- Rb
- PWM/GPIO
- (Pin 40)
- (Pin 20)
- GND
- PWR +3.3V
- (Pin 01)
- (Pin 21)
- PWR +5V
- PWM/GPIO
- (Pin 39)
- (Pin 19)
- GPIO/SPI_CS
- Ra
- GPIO/ADC_IN
- (Pin 02)
- (Pin 22)
- GND
- PWM/GPIO
- (Pin 38)
- (Pin 18)
- GPIO/SPI_CS
- GPIO/UART_RXD
- (Pin 03)
- (Pin 23)
- ADC_IN
- PWM/UART_RTS
- (Pin 37)
- (Pin 17)
- GPIO/UART_TXD
- (Pin 04)
- (Pin 24)
- ADC_IN
- PWM/UART_CTS
- (Pin 36)
- (Pin 16)
- RESET
- GPIO
- GPIO/UART_RXD
- (Pin 05)
- (Pin 06)
- (Pin 25)
- (Pin 26)
- ADC_IN
- ADC_IN
- Rc
- PWM/GPIO
- UART_RTS
- (Pin 34)
- (Pin 35)
- (Pin 14)
- (Pin 15)
- SPI_MISO
- SPI_MOSI
- SPI_CLK/UART_TXD
- (Pin 07)
- (Pin 27)
- ADC_IN/I2S_WCLK
- UART_CTS
- (Pin 33)
- (Pin 13)
- GPIO/PWM
- Rf
- GPIO
- (Pin 08)
- (Pin 28)
- ADC_IN/I2S_BCLK
- Rl
- Rd
- (Pin 32)
- (Pin 12)
- GPIO/PWM
- PWM/GPIO
- (Pin 09)
- (Pin 29)
- ADC_IN/I2S_DOUT
- (Pin 31)
- (Pin 11)
- GPIO
- Re
- PWM/GPIO
- (Pin 10)
- (Pin 30)
- I2S_DIN
- Rk
- Rj
- Ri
- Rh
- Rg
- Silkscreen:
  "BP-RHS HDR"
- Silkscreen:
  "BP-LHS HDR"
- NOTE: Except BOOST-DRV8848 all other below listed BP
   interfaces supported similar to maxwell EVM
- Supported Booster Packs
- Part to be mounted
- Part not be mounted
- S.No
- 1
- BOOSTXL-ULN2003
- Ra
- Rb
- 2
- BOOST-DRV8711
- Rb
- Ra
- 3
- BOOSTXL-DRV8301
- Rc
- Rd
- 4
- CC3100BOOST
- Rd
- Rc
- 5
- BOOST-CC2564MODA
- Rd
- Rf
- Rh
- Rj
- Rl
- Rc
- Re
- Rg
- Ri
- Rk
- FROM CPB DIP SW3.8
sheet 21
- ADC IN
